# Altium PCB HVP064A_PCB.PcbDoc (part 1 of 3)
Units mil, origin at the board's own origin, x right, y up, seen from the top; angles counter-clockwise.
Board outline 5750 x 4500 mil, 2 copper layers (Top Layer, Bottom Layer), stack 62 mil thick; 174 components, 71 nets, 376 pads, 361 vias.
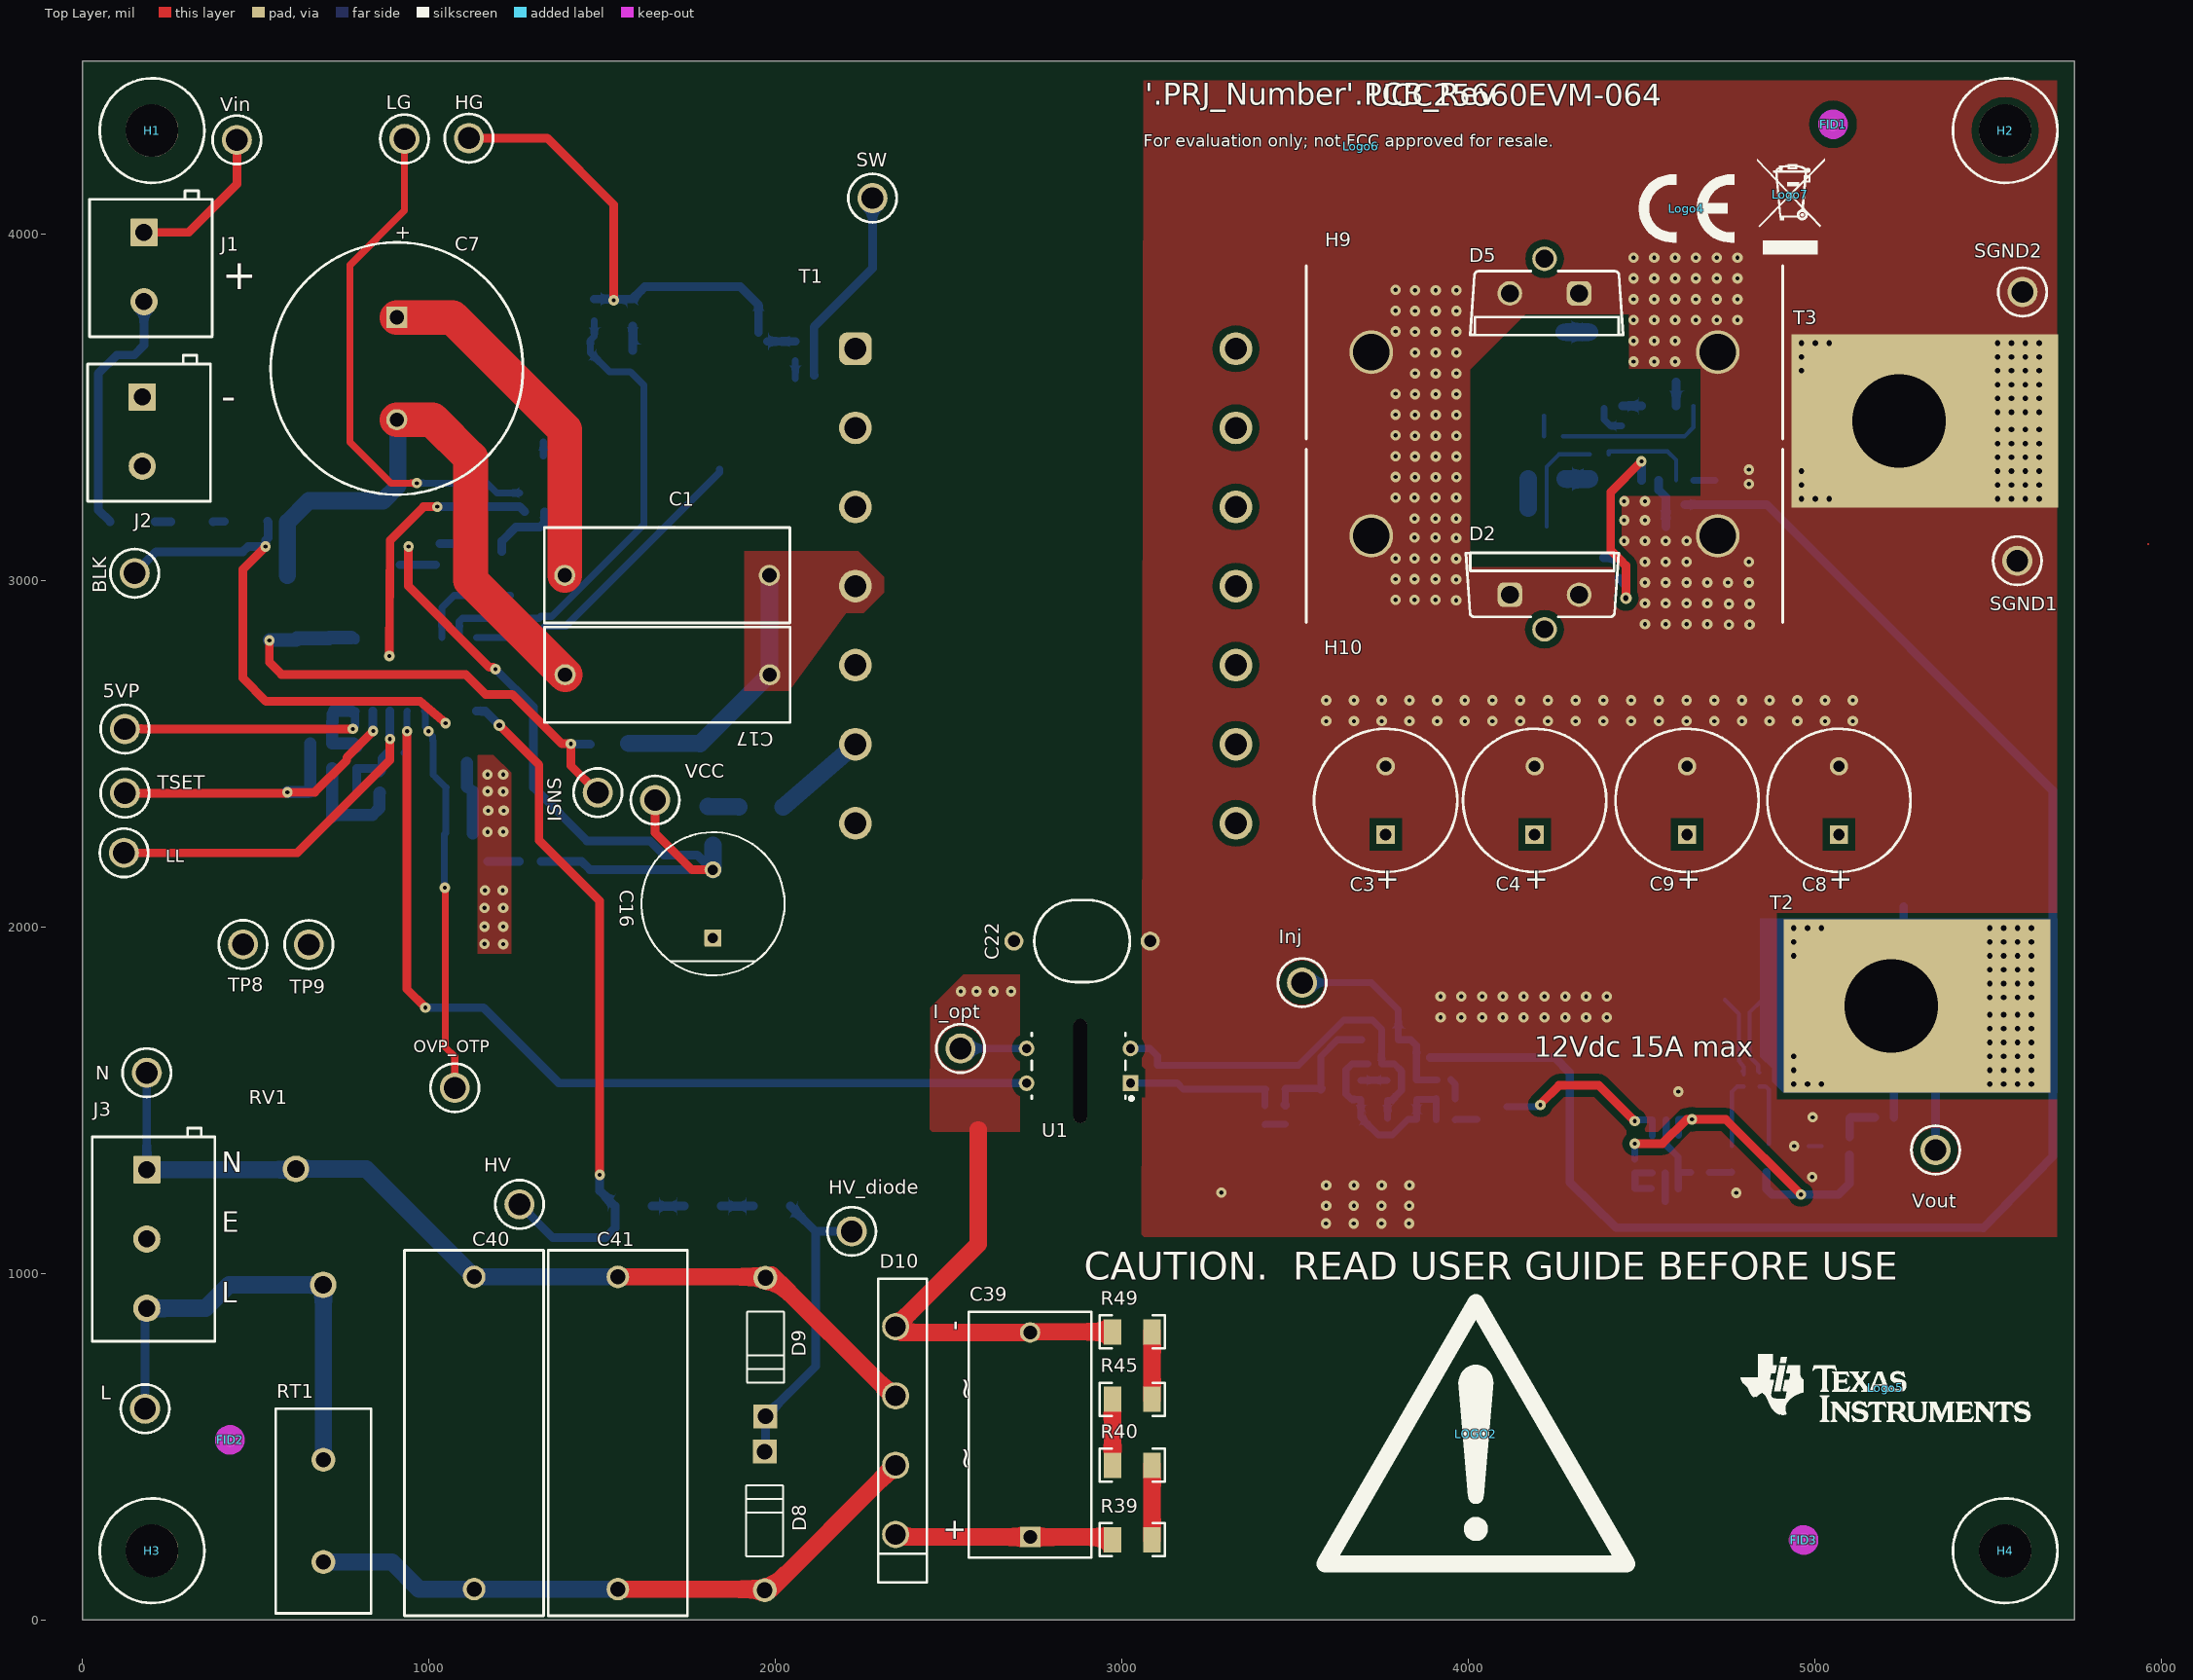
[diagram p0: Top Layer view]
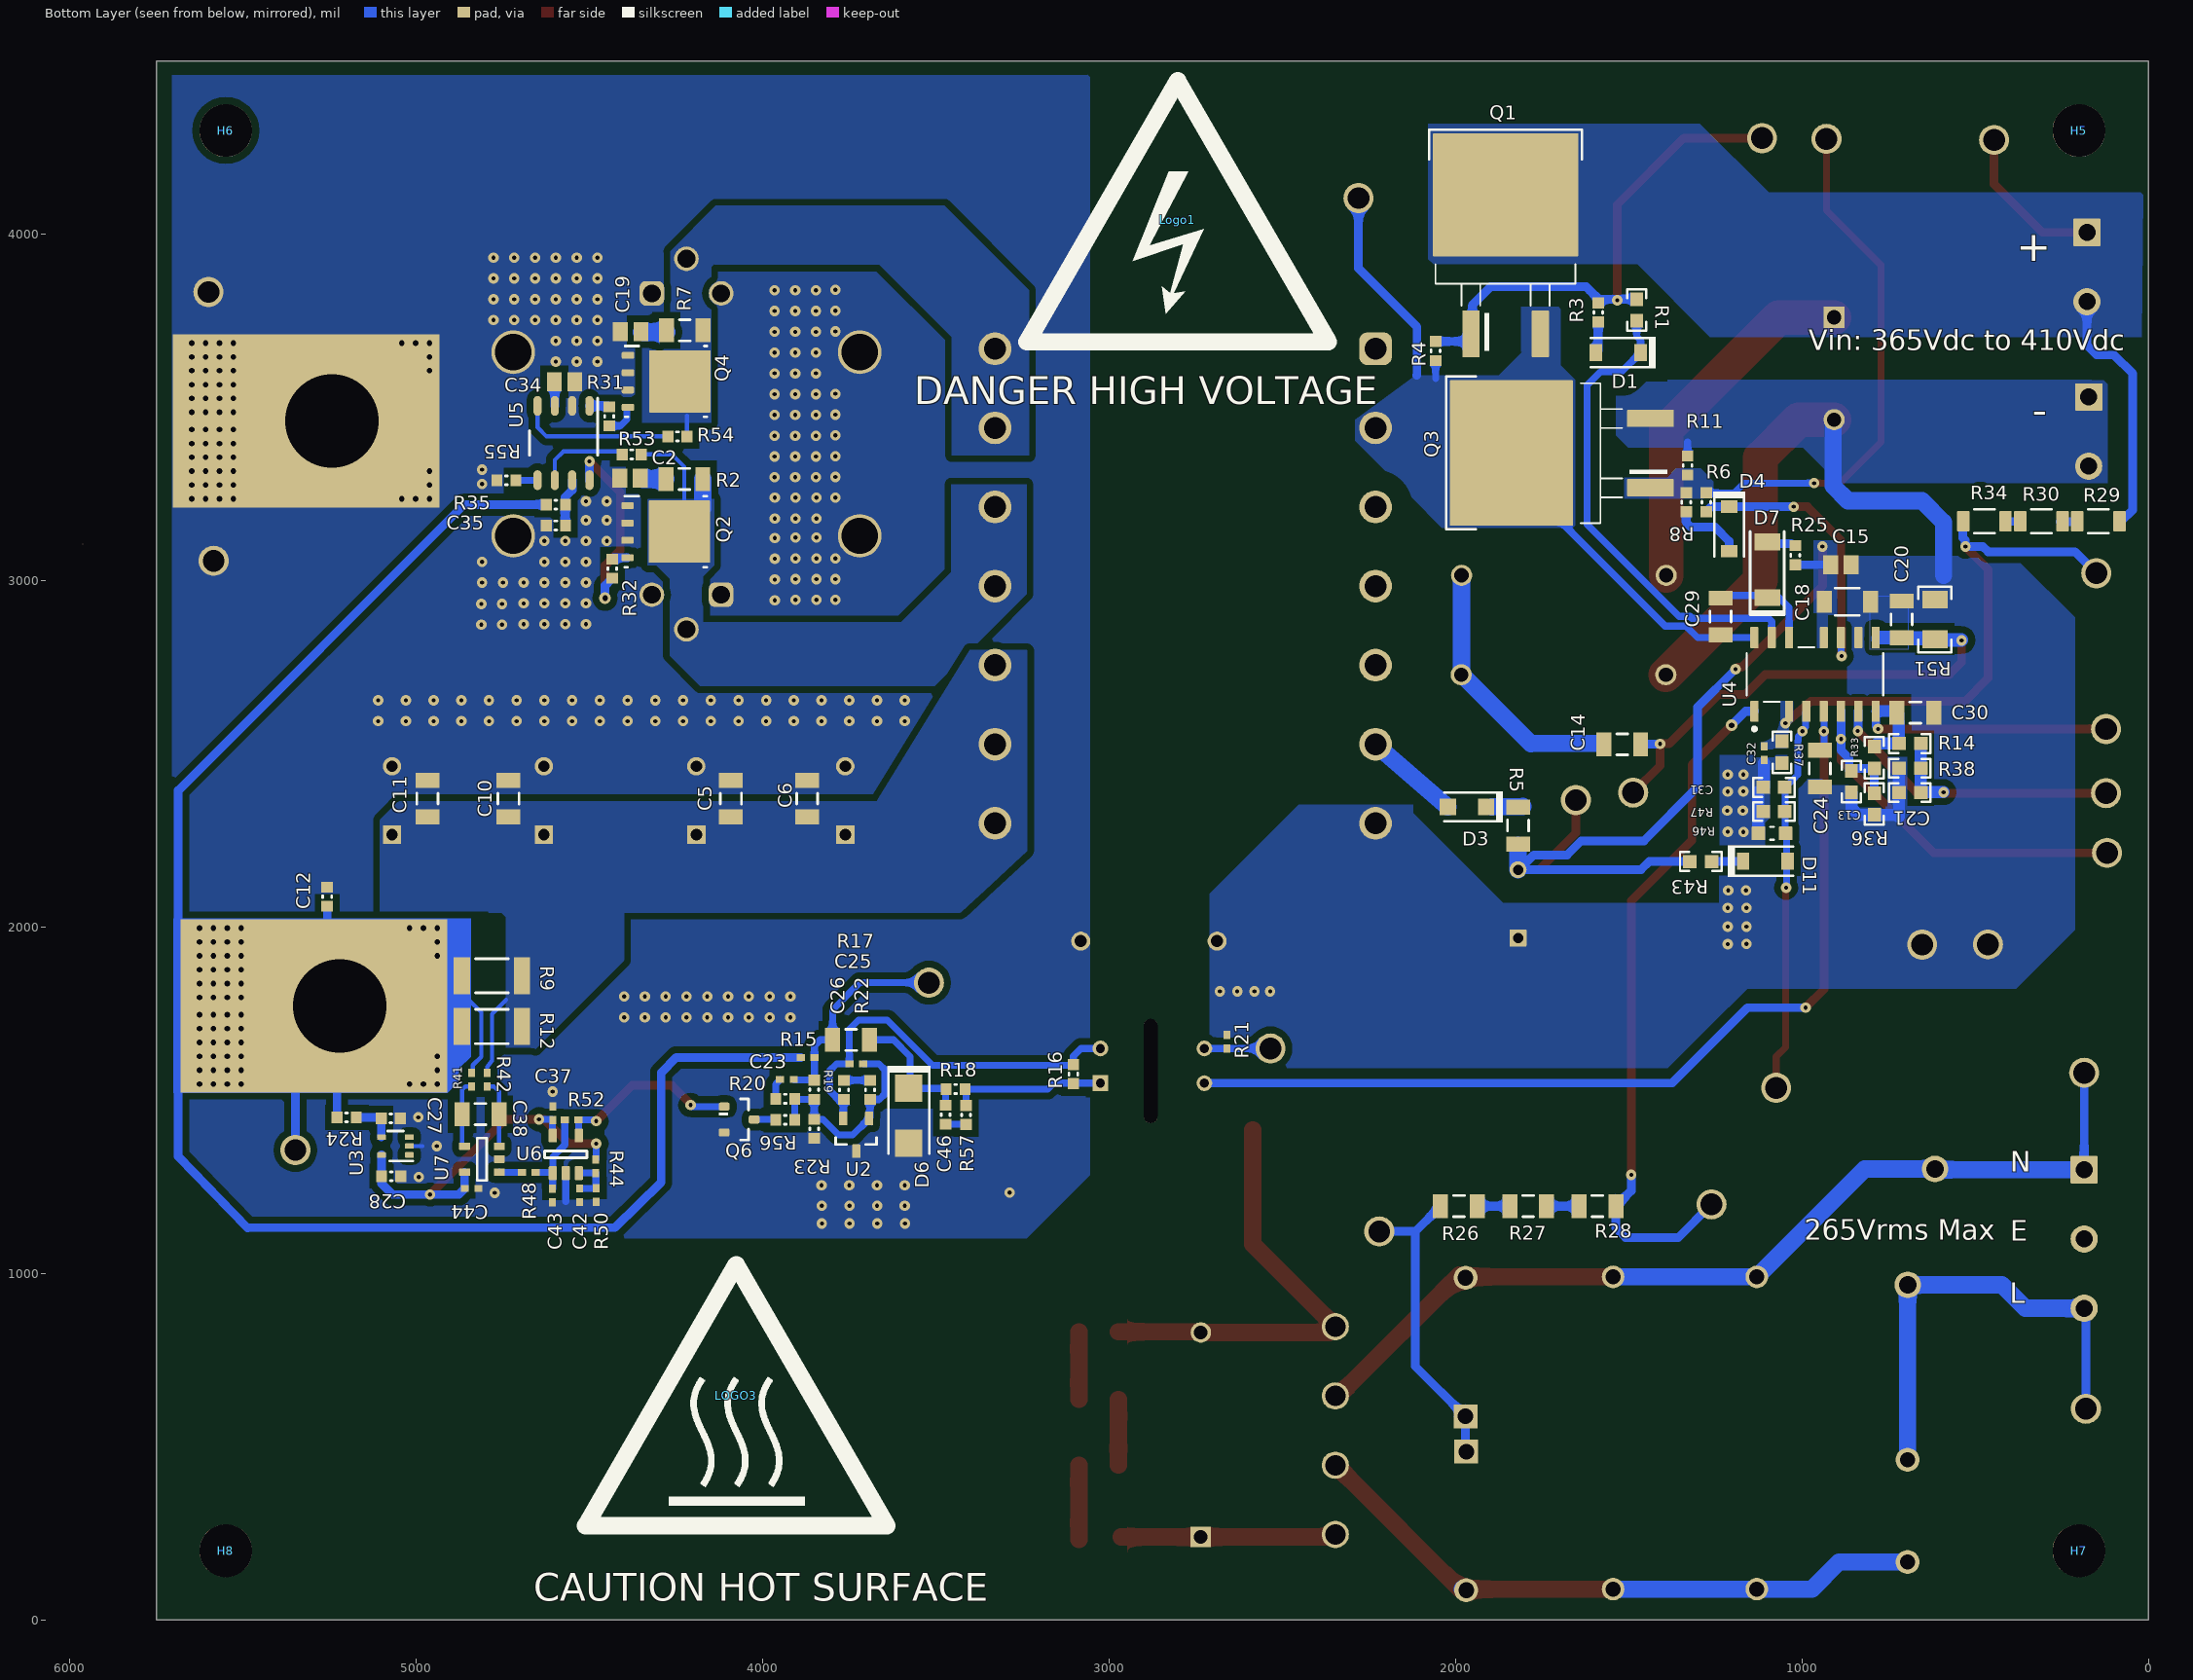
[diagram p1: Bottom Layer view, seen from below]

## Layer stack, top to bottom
Top Solder: solder mask 0.4, Solder Resist, Dk 3.5
Top Layer: signal copper 2.8
Dielectric1: core 56.4, FR-4 High Tg, Dk 4.8
Bottom Layer: signal copper 2.8
Bottom Solder: solder mask 0.4, Solder Resist, Dk 3.5

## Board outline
0,0 5750,0 5750,4500 0,4500

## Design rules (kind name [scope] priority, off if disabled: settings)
AcuteAngle [All] p1: minimum=4.50000000000000E+0001 checktracksonly=FALSE
AssemblyTestPointUsage [All] p1: valid=2
Clearance Clearance_2 [InNetClass('HV') vs Not InNetClass('HV')] p1: gap=60 ignorepadtopadclearanceinfootprint=TRUE except(0: Arc-Hole Track-Hole SMDPad-Hole THPad-Hole Via-Hole Fill-Hole Poly-Hole Region-Hole Text-Hole)
Clearance Clearance_1 [InNetClass('MV') vs Not InNetClass('MV')] p2: gap=40 ignorepadtopadclearanceinfootprint=TRUE
Clearance Clearance_Keepouts [((IsTrack Or IsArc) And Not InPoly) And IsFree and IsKeepOut vs ((IsTrack Or IsArc) And Not InPoly) And IsFree and IsKeepOut] p3: gap=0 ignorepadtopadclearanceinfootprint=FALSE
Clearance Clearance_BoardEdge_MountingHoles [OnCopper and InComponentClass('Mounting Holes') vs IsKeepOut] p4: gap=40 ignorepadtopadclearanceinfootprint=FALSE except(0: Arc-Hole Track-Hole SMDPad-Hole THPad-Hole Via-Hole Fill-Hole Poly-Hole Region-Hole Text-Hole)
Clearance Clearance_BoardEdge_Poly [OnCopper and InPoly vs IsKeepOut] p5: gap=25 ignorepadtopadclearanceinfootprint=FALSE except(0: Arc-Hole Track-Hole SMDPad-Hole THPad-Hole Via-Hole Fill-Hole Poly-Hole Region-Hole Text-Hole)
Clearance Clearance_BoardEdge [OnCopper and Not InComponentClass('Logo') and not InComponentClass('FiducialMark') and not InRegion(1000,500,4000,800) and Not IsKeepout vs IsKeepOut] p6: gap=75 ignorepadtopadclearanceinfootprint=FALSE except(0: Arc-Hole Track-Hole SMDPad-Hole THPad-Hole Via-Hole Fill-Hole Poly-Hole Region-Hole Text-Hole)
Clearance Clearance_Poly [InPolygon] p7: gap=20 ignorepadtopadclearanceinfootprint=FALSE except(0: Arc-Hole Track-Hole SMDPad-Hole THPad-Hole Via-Hole Fill-Hole Poly-Hole Region-Hole Text-Hole)
Clearance [All] p8: gap=7.87 ignorepadtopadclearanceinfootprint=FALSE except(0: Arc-SMDPad Arc-Hole Track-Hole SMDPad-Hole THPad-Hole Via-Hole Fill-Hole Poly-Hole Region-Hole Text-Hole)
ComponentClearance ComponentClearance_MountingHoles_FiducialMarks [InComponentClass('Mounting Holes') vs InComponentClass('FiducialMark')] p1: gap=20 collisioncheckmode=3 verticalgap=7 showdistances=FALSE
ComponentClearance ComponentClearance_Shunt [InComponentClass('Header') vs InComponentClass('Shunt')] p2: gap=0 collisioncheckmode=3 verticalgap=0 showdistances=FALSE
ComponentClearance ComponentClearance_Logo [InComponentClass('Logo')] p3: gap=5 collisioncheckmode=3 verticalgap=10 showdistances=FALSE
ComponentClearance ComponentClearance_ScrewToNut [(HasFootprint('KEYSTONE_4824')) vs (HasFootprint('Keystone_1903C'))] p4: gap=0 collisioncheckmode=3 verticalgap=0 showdistances=FALSE
ComponentClearance ComponentClearance_MountingHoles [InComponentClass('Mounting Holes')] p5: gap=20 collisioncheckmode=3 verticalgap=7 showdistances=FALSE
ComponentClearance ComponentClearance_SmallPassives [HasFootprint('0201*') or HasFootprint('0402*') or HasFootprint('0508') or HasFootprint('0603*') or HasFootprint('0612') or HasFootprint('0805*') or HasFootprint('0815*') or HasFootprint('0830*') or HasFootprint('1206*') or HasFootprint('1210*') or HasFootprint('1808*') or HasFootprint('1812*') or HasFootprint('1825*') or HasFootprint('2010*') or HasFootprint('2220*') or HasFootprint('2225*') or HasFootprint('2512*') or HasFootprint('2728*') or HasFootprint('3518*') vs HasFootprint('0201*') or HasFootprint('0402*') or HasFootprint('0508') or HasFootprint('0603*') or HasFootprint('0612') or HasFootprint('0805*') or HasFootprint('0815*') or HasFootprint('0830*') or HasFootprint('1206*') or HasFootprint('1210*') or HasFootprint('1808*') or HasFootprint('1812*') or HasFootprint('1825*') or HasFootprint('2010*') or HasFootprint('2220*') or HasFootprint('2225*') or HasFootprint('2512*') or HasFootprint('2728*') or HasFootprint('3518*')] p6: gap=20 collisioncheckmode=3 verticalgap=20 showdistances=FALSE
ComponentClearance ComponentClearance_THtoSMT [IsThruComponent vs IsSMTComponent] p7: gap=10 collisioncheckmode=3 verticalgap=7 showdistances=FALSE
ComponentClearance ComponentClearance_THtoTH [IsThruComponent vs IsThruComponent] p8: gap=10 collisioncheckmode=3 verticalgap=7 showdistances=FALSE
ComponentClearance [All] p9: gap=10 collisioncheckmode=3 verticalgap=7 showdistances=FALSE
DiffPairsRouting [All] p1: maxlimit=100 minlimit=10 mostfreqgap=10 toplayer_minwidth=15 toplayer_maxwidth=15 toplayer_prefwidth=15 bottomlayer_minwidth=15 bottomlayer_maxwidth=15 bottomlayer_prefwidth=15 maxuncoupledlength=1000
FabricationTestPointUsage TestPointUsage [All] p1: valid=2 allowmultiple=FALSE
FabricationTestpoint Testpoint [All] p1: side=3 testpointundercomponent=TRUE minsize=40 maxsize=100 preferedsize=60 minholesize=0 maxholesize=40 preferedholesize=32 testpointgrid=1 allowsidetop=TRUE allowsidebottom=TRUE usegrid=TRUE gridtolerance=0.01
FanoutControl Fanout_LCC [IsLCC] p1: bgadir=Out bgaviamode=Centered fanoutstyle=Auto fanoutdirection=Alternating viagrid=1 // Fanout_LCC (Default Rule)
FanoutControl Fanout_BGA [IsBGA] p2: bgadir=Out bgaviamode=Centered fanoutstyle=Auto fanoutdirection=Alternating viagrid=1 // Fanout_BGA (Default Rule)
FanoutControl Fanout_Default [All] p4: bgadir=Out bgaviamode=Centered fanoutstyle=Auto fanoutdirection=Alternating viagrid=1 // Fanout_Default (Default Rule)
FanoutControl Fanout_Small [(CompPinCount < 5)] p5: bgadir=Out bgaviamode=Centered fanoutstyle=Auto fanoutdirection=OutThenIn viagrid=1 // Fanout_Small (Default Rule)
Height [All] p1: minheight=0 maxheight=3000 prefheight=500
HoleSize [All] p1: absolutevalues=TRUE maxlimit=501 minlimit=7 maxpercent=80.000 minpercent=20.000
MinimumAnnularRing MinimumAnnularRing_ThermalPadVias [IsVia and InAnyComponent] p1: minimumring=5.91
MinimumAnnularRing [All] p2: minimumring=5
MinimumSolderMaskSliver MinimumSolderMaskSliver_Logo [InComponentClass('Logo') vs InComponentClass('Logo')] p1: minsoldermaskwidth=0.7
MinimumSolderMaskSliver [All] p2: minsoldermaskwidth=3
PlaneConnect [All] p1: planeconnectstyle=Direct reliefexpansion=10 reliefentries=4 reliefconductorwidth=10 reliefairgap=10
PolygonConnect PolygonConnect_16 [All vs IsNamedPolygon('C106_2') Or  IsNamedPolygon('Vout') Or  IsNamedPolygon('IN+') Or  IsNamedPolygon('Q203_5') Or  IsNamedPolygon('IN+') Or  IsNamedPolygon('Q201_5') Or  IsNamedPolygon('C108_2') Or  IsNamedPolygon('SGND') Or  IsNamedPolygon('IN+') Or  IsNamedPolygon('SGND') Or  IsNamedPolygon('Q203_5') Or  IsNamedPolygon('IN+') Or  IsNamedPolygon('SGND') Or  IsNamedPolygon('GND') Or  IsNamedPolygon('C113_2') Or  IsNamedPolygon('C107_2') Or  IsNamedPolygon('C107_2') Or  IsNamedPolygon('Vout') Or  IsNamedPolygon('SIGNAL_LAYER_1_GND_P074') Or  IsNamedPolygon('HV') Or  IsNamedPolygon('C108_2') Or  IsNamedPolygon('C103_2') Or  IsNamedPolygon('Q201_5') Or  IsNamedPolygon('Vout') Or  IsNamedPolygon('C109_2') Or  IsNamedPolygon('Q201_5') Or  IsNamedPolygon('GND') Or  IsNamedPolygon('C107_2') Or  IsNamedPolygon('C102_1') Or  IsNamedPolygon('GND') Or  IsNamedPolygon('SGND') Or  IsNamedPolygon('HS') Or  IsNamedPolygon('Q203_5') Or  IsNamedPolygon('Q201_5') Or  IsNamedPolygon('Q203_5')] p1: connectstyle=Direct reliefconductorwidth=10 reliefentries=4 polygonreliefangle="90 Angle" airgapwidth=10
PolygonConnect PolygonConnect_15 [All vs IsNamedPolygon('C109_2') Or  IsNamedPolygon('C107_2') Or  IsNamedPolygon('HV') Or  IsNamedPolygon('Q203_5') Or  IsNamedPolygon('C107_2') Or  IsNamedPolygon('HS') Or  IsNamedPolygon('Q201_5') Or  IsNamedPolygon('Q203_5') Or  IsNamedPolygon('C106_2') Or  IsNamedPolygon('C108_2') Or  IsNamedPolygon('Vout') Or  IsNamedPolygon('Q203_5') Or  IsNamedPolygon('C108_2') Or  IsNamedPolygon('C113_2') Or  IsNamedPolygon('Q203_5') Or  IsNamedPolygon('Q201_5') Or  IsNamedPolygon('C107_2') Or  IsNamedPolygon('C102_1') Or  IsNamedPolygon('SGND') Or  IsNamedPolygon('GND') Or  IsNamedPolygon('SGND') Or  IsNamedPolygon('GND') Or  IsNamedPolygon('IN+') Or  IsNamedPolygon('IN+') Or  IsNamedPolygon('Q201_5') Or  IsNamedPolygon('Q201_5') Or  IsNamedPolygon('SGND') Or  IsNamedPolygon('SGND') Or  IsNamedPolygon('Vout') Or  IsNamedPolygon('Vout') Or  IsNamedPolygon('IN+') Or  IsNamedPolygon('GND') Or  IsNamedPolygon('IN+') Or  IsNamedPolygon('GND')] p2: connectstyle=Direct reliefconductorwidth=10 reliefentries=4 polygonreliefangle="90 Angle" airgapwidth=10
PolygonConnect PolygonConnect_14 [All vs IsNamedPolygon('C106_2') Or  IsNamedPolygon('C107_2') Or  IsNamedPolygon('C107_2') Or  IsNamedPolygon('C107_2') Or  IsNamedPolygon('C102_1') Or  IsNamedPolygon('Q203_5') Or  IsNamedPolygon('Vout') Or  IsNamedPolygon('Q203_5') Or  IsNamedPolygon('Q203_5') Or  IsNamedPolygon('Q201_5') Or  IsNamedPolygon('C108_2') Or  IsNamedPolygon('Q203_5') Or  IsNamedPolygon('HS') Or  IsNamedPolygon('HV') Or  IsNamedPolygon('C108_2') Or  IsNamedPolygon('Q201_5') Or  IsNamedPolygon('C109_2') Or  IsNamedPolygon('Q201_5') Or  IsNamedPolygon('Q201_5') Or  IsNamedPolygon('C113_2')] p3: connectstyle=Direct reliefconductorwidth=10 reliefentries=4 polygonreliefangle="90 Angle" airgapwidth=10
PolygonConnect PolygonConnect_13 [All vs IsNamedPolygon('C102_1') Or  IsNamedPolygon('HV') Or  IsNamedPolygon('C107_2') Or  IsNamedPolygon('C109_2') Or  IsNamedPolygon('C107_2') Or  IsNamedPolygon('C108_2') Or  IsNamedPolygon('C106_2') Or  IsNamedPolygon('C108_2') Or  IsNamedPolygon('C113_2') Or  IsNamedPolygon('C107_2')] p4: connectstyle=Direct reliefconductorwidth=10 reliefentries=4 polygonreliefangle="90 Angle" airgapwidth=10
PolygonConnect PolygonConnect_12 [All vs IsNamedPolygon('C107_2') Or  IsNamedPolygon('C113_2') Or  IsNamedPolygon('C106_2') Or  IsNamedPolygon('C107_2') Or  IsNamedPolygon('C107_2') Or  IsNamedPolygon('C102_1')] p5: connectstyle=Direct reliefconductorwidth=10 reliefentries=4 polygonreliefangle="90 Angle" airgapwidth=10
PolygonConnect PolygonConnect_11 [All vs IsNamedPolygon('C106_2') Or  IsNamedPolygon('C102_1') Or  IsNamedPolygon('C107_2') Or  IsNamedPolygon('C107_2') Or  IsNamedPolygon('C107_2')] p6: connectstyle=Direct reliefconductorwidth=10 reliefentries=4 polygonreliefangle="90 Angle" airgapwidth=10
PolygonConnect PolygonConnect_10 [All vs IsNamedPolygon('C106_2')] p7: connectstyle=Direct reliefconductorwidth=10 reliefentries=4 polygonreliefangle="90 Angle" airgapwidth=10
PolygonConnect PolygonConnect_9 [All vs IsNamedPolygon('C11_1') Or  IsNamedPolygon('Vin') Or  IsNamedPolygon('Vin') Or  IsNamedPolygon('5V') Or  IsNamedPolygon('D6_2') Or  IsNamedPolygon('Q3_3') Or  IsNamedPolygon('GND2') Or  IsNamedPolygon('GND2') Or  IsNamedPolygon('GND') Or  IsNamedPolygon('Q3_4') Or  IsNamedPolygon('12V5') Or  IsNamedPolygon('GND') Or  IsNamedPolygon('12V5') Or  IsNamedPolygon('D3_1')] p8: connectstyle=Direct reliefconductorwidth=10 reliefentries=4 polygonreliefangle="90 Angle" airgapwidth=10
PolygonConnect PolygonConnect_8 [All vs IsNamedPolygon('C11_1') Or  IsNamedPolygon('Vin') Or  IsNamedPolygon('12V5') Or  IsNamedPolygon('Q3_3') Or  IsNamedPolygon('GND2') Or  IsNamedPolygon('GND2') Or  IsNamedPolygon('5V') Or  IsNamedPolygon('Q3_4') Or  IsNamedPolygon('12V5')] p9: connectstyle=Direct reliefconductorwidth=10 reliefentries=4 polygonreliefangle="90 Angle" airgapwidth=10
PolygonConnect PolygonConnect_7 [All vs IsNamedPolygon('GND2') Or  IsNamedPolygon('GND2') Or  IsNamedPolygon('5V') Or  IsNamedPolygon('12V5') Or  IsNamedPolygon('12V5') Or  IsNamedPolygon('C11_1')] p10: connectstyle=Direct reliefconductorwidth=10 reliefentries=4 polygonreliefangle="90 Angle" airgapwidth=10
PolygonConnect PolygonConnect_6 [All vs IsNamedPolygon('GND2') Or  IsNamedPolygon('SGND') Or  IsNamedPolygon('GND1') Or  IsNamedPolygon('C901_1') Or  IsNamedPolygon('SGND') Or  IsNamedPolygon('GND2') Or  IsNamedPolygon('GND1')] p11: connectstyle=Direct reliefconductorwidth=10 reliefentries=4 polygonreliefangle="90 Angle" airgapwidth=10
PolygonConnect PolygonConnect_5 [All vs IsNamedPolygon('GND1') Or  IsNamedPolygon('GND1')] p12: connectstyle=Direct reliefconductorwidth=10 reliefentries=4 polygonreliefangle="90 Angle" airgapwidth=10
PolygonConnect PolygonConnect_4 [All vs IsNamedPolygon('C21_1') Or  IsNamedPolygon('C5_1') Or  IsNamedPolygon('C12_2') Or  IsNamedPolygon('C2_2') Or  IsNamedPolygon('C13_1') Or  IsNamedPolygon('C28_1') Or  IsNamedPolygon('C6_1') Or  IsNamedPolygon('GND') Or  IsNamedPolygon('GND2') Or  IsNamedPolygon('C14_1') Or  IsNamedPolygon('C13_1') Or  IsNamedPolygon('Q1_3') Or  IsNamedPolygon('C14_1') Or  IsNamedPolygon('C5_1') Or  IsNamedPolygon('GND2') Or  IsNamedPolygon('C28_1') Or  IsNamedPolygon('D5_2') Or  IsNamedPolygon('D6_2') Or  IsNamedPolygon('D2_1') Or  IsNamedPolygon('C12_2') Or  IsNamedPolygon('D2_1') Or  IsNamedPolygon('C4_1') Or  IsNamedPolygon('C4_1') Or  IsNamedPolygon('C2_2') Or  IsNamedPolygon('GND') Or  IsNamedPolygon('C33_1') Or  IsNamedPolygon('C9_1')] p13: connectstyle=Direct reliefconductorwidth=10 reliefentries=4 polygonreliefangle="90 Angle" airgapwidth=10
PolygonConnect PolygonConnect_3 [All vs IsNamedPolygon('C28_1') Or  IsNamedPolygon('C12_2') Or  IsNamedPolygon('C28_1') Or  IsNamedPolygon('C9_1') Or  IsNamedPolygon('D5_2') Or  IsNamedPolygon('C12_2') Or  IsNamedPolygon('C2_2') Or  IsNamedPolygon('C14_1') Or  IsNamedPolygon('C4_1') Or  IsNamedPolygon('C14_1') Or  IsNamedPolygon('D6_2') Or  IsNamedPolygon('GND2') Or  IsNamedPolygon('Q1_3') Or  IsNamedPolygon('C5_1') Or  IsNamedPolygon('D2_1') Or  IsNamedPolygon('C4_1') Or  IsNamedPolygon('C13_1') Or  IsNamedPolygon('C5_1') Or  IsNamedPolygon('C13_1') Or  IsNamedPolygon('C33_1') Or  IsNamedPolygon('D2_1') Or  IsNamedPolygon('GND') Or  IsNamedPolygon('GND') Or  IsNamedPolygon('GND2') Or  IsNamedPolygon('C2_2') Or  IsNamedPolygon('C6_1') Or  IsNamedPolygon('C21_1')] p14: connectstyle=Direct reliefconductorwidth=10 reliefentries=4 polygonreliefangle="90 Angle" airgapwidth=10
PolygonConnect PolygonConnect_2 [All vs IsNamedPolygon('C21_1') Or  IsNamedPolygon('C4_1') Or  IsNamedPolygon('D5_2') Or  IsNamedPolygon('C5_1') Or  IsNamedPolygon('C14_1') Or  IsNamedPolygon('C13_1') Or  IsNamedPolygon('C4_1') Or  IsNamedPolygon('C33_1') Or  IsNamedPolygon('C12_2') Or  IsNamedPolygon('D2_1') Or  IsNamedPolygon('C2_2') Or  IsNamedPolygon('C28_1') Or  IsNamedPolygon('C12_2') Or  IsNamedPolygon('D2_1') Or  IsNamedPolygon('C5_1') Or  IsNamedPolygon('Q1_3') Or  IsNamedPolygon('GND') Or  IsNamedPolygon('D6_2') Or  IsNamedPolygon('C6_1') Or  IsNamedPolygon('C2_2') Or  IsNamedPolygon('C14_1') Or  IsNamedPolygon('C28_1') Or  IsNamedPolygon('C13_1') Or  IsNamedPolygon('C9_1') Or  IsNamedPolygon('GND')] p15: connectstyle=Direct reliefconductorwidth=10 reliefentries=4 polygonreliefangle="90 Angle" airgapwidth=10
PolygonConnect PolygonConnect_1 [All vs IsNamedPolygon('C28_1') Or  IsNamedPolygon('D5_2') Or  IsNamedPolygon('C5_1') Or  IsNamedPolygon('C5_1') Or  IsNamedPolygon('D2_1') Or  IsNamedPolygon('C21_1') Or  IsNamedPolygon('C9_1') Or  IsNamedPolygon('C4_1') Or  IsNamedPolygon('C14_1') Or  IsNamedPolygon('C28_1') Or  IsNamedPolygon('C6_1') Or  IsNamedPolygon('C12_2') Or  IsNamedPolygon('C33_1') Or  IsNamedPolygon('C4_1') Or  IsNamedPolygon('C13_1') Or  IsNamedPolygon('C12_2') Or  IsNamedPolygon('D6_2') Or  IsNamedPolygon('C2_2') Or  IsNamedPolygon('C14_1') Or  IsNamedPolygon('D2_1') Or  IsNamedPolygon('C2_2') Or  IsNamedPolygon('C13_1')] p16: connectstyle=Direct reliefconductorwidth=10 reliefentries=4 polygonreliefangle="90 Angle" airgapwidth=10
PolygonConnect [All] p17: connectstyle=Direct reliefconductorwidth=10 reliefentries=4 polygonreliefangle="90 Angle" airgapwidth=10
RoutingVias ThermalPadVias [IsVia and not InNet('SGND')and not InNet('Vout')] p1: holewidth=7.87 width=19.68 viastyle="Through Hole" minholewidth=7.87 minwidth=19.68 maxholewidth=17 maxwidth=35
RoutingVias [IsVia and not InNet('SGND')and not InNet('Vout')] p2: holewidth=16 width=34 viastyle="Through Hole" minholewidth=7.87 minwidth=20 maxholewidth=40 maxwidth=65
SilkToBoardRegionClearance [Not ((IsComment or IsDesignator) And (Hide <> 'False')) and not InRegion(1000,500,4000,800)] p1:
SilkToSilkClearance SilkToSilkClearance_Pb-FreeLogo [(HasFootprint('Pb-Free_Overlay_Medium') OR HasFootprint('Pb-Free_Overlay_Small')) vs (HasFootprint('Pb-Free_Overlay_Medium') OR HasFootprint('Pb-Free_Overlay_Small'))] p1: silktosilkclearance=0
SilkToSilkClearance [All] p2: silktosilkclearance=3
SilkToSolderMaskClearance "Silk to Solder Mask Opening" [All] p1: minsilkscreentomaskgap=1 clearancetoexposedcopper=FALSE
SolderMaskExpansion [All] p1: expansion=1.97 istentingtop=FALSE
UnpouredPolygon [All] p1: allowunpoured=TRUE allowshelved=TRUE
Width [All] p1: maxlimit=100 minlimit=6 preferedwidth=10 checkconnectedcopper=TRUE
13 further rules are at their usual default settings.

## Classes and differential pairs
net class MV: NetR29_1 NetR30_1
net class HV: HO HS NetC1_2 NetC29_1 NetC39_1 NetC40_1 NetC40_2 NetD1_2 NetD8_1 NetHG_1 NetHV_1 NetJ3_3 VIN
component class HVP064A_Control: 5VP BLK C13 C21 C27 C28 C29 C30 C31 C32 C34 C35 C37 C38 C39 C40 C41 C42 C43 C44 D7 D8 D9 D10 D11 HV HV_diode J3 L LL N OVP_OTP R14 R24 R25 R26 R27 R28 R29 R30 R31 R32 R33 R34 R35 R36 R37 R38 R39 R40 R41 R42 R43 R44 R45 R46 R47 R48 R49 R50 R52 R53 R54 R55 RT1 RV1 TSET U3 U4 U5 U6 U7
component class HVP064A_PowerStage: C1 C2 C3 C4 C5 C6 C7 C8 C9 C10 C11 C12 C14 C15 C16 C17 C18 C19 C20 C22 C23 C24 C25 C26 C46 D1 D2 D3 D4 D5 D6 H9 H10 HG I_opt Inj ISNS J1 J2 LG Q1 Q2 Q3 Q4 Q6 R1 R2 R3 R4 R5 R6 R7 R8 R9 R11 R12 R15 R16 R17 R18 R19 R20 R21 R22 R23 R51 R56 R57 SGND1 SGND2 SW T1 T2 T3 TP8 TP9 U1 U2 VCC Vin Vout
component class AssemblyNote: ZZ1 ZZ2 ZZ3
component class FiducialMark: FID1 FID2 FID3
component class HVP064A_EVM_Hardware: FID1 FID2 FID3 H1 H2 H3 H4 H5 H6 H7 H8 Logo1 LOGO2 LOGO3 Logo4 LOGO4 Logo5 Logo6 Logo7 ZZ1 ZZ2 ZZ3
component class Logo: Logo5

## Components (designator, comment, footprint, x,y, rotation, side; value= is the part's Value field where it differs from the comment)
5VP "5010" Keystone5010 122,2572.19 r0 top
BLK "5012" Keystone5012 150,3022 r0 top
C1 "B32652A7153J000" B32652_1800x700x1250 1687,3016 r0 top value=0.015uF
C2 "GRM2165C2A122JA01D" 0805L 4383,3297 r0 bottom value=1200pF
C3 "UHW1V471MPD" HW_1000x1600 3761.61,2366.26 r90 top value=470uF
C4 "UHW1V471MPD" HW_1000x1600 4191.61,2366.26 r90 top value=470uF
C5 "C3216X5R1E226M160AB" 1206_190L 4091.61,2371.26 r270 bottom value=22uF
C6 "C3216X5R1E226M160AB" 1206_190L 3871.61,2371.26 r270 bottom value=22uF
C7 "EKXG451ELL680MMN3S" KXG_1800x3150 907,3613 r270 top value=68uF
C8 "UHW1V471MPD" HW_1000x1600 5070,2366.26 r90 top value=470uF
C9 "UHW1V471MPD" HW_1000x1600 4631.61,2366.26 r90 top value=470uF
C10 "C3216X5R1E226M160AB" 1206_190L 4734,2371.26 r90 bottom value=22uF
C11 "C3216X5R1E226M160AB" 1206_190L 4968,2371.26 r90 bottom value=22uF
C12 "06035A101FAT2A" 0603L 5257,2088 r90 bottom value=100pF
C13 "C0603X102K5RACTU" 0603 857.34,2420.41 r270 bottom value=1000pF
C14 "GRM31A5C2J151JW01D" 1206L 1518.58,2528 r180 bottom value=150pF
C15 "C2012X7R1V225K085AC" 0805L 886.87,3046.51 r180 bottom value=2.2uF
C16 "35ZL330MEFC10X16" FP-35ZL330MEFC10X16_RADIAL-MFG 1819.55,2067.71 r90 top value=330µF
C17 "B32652A7153J000" B32652_1800x700x1250 1688,2729 r180 top value=0.015uF
C18 "C1206C106J3RACAUTO" 1206_180 868.61,2939.49 r180 bottom value=10uF
C19 "GRM2165C2A122JA01D" 0805L 4381,3719 r0 bottom value=1200pF
C20 "12061A101JAT2A" 1206L 712,2888.61 r90 bottom value=100pF
C21 "C0603X221K5RACTU" 0603 688.17,2388.92 r0 bottom value=220pF
C22 "CD45-E2GA102M-NKA" CD45_700x600x1100 2885,1960 r180 top value=1000pF
C23 "885012005062" 0402L 3930,1560 r0 bottom value=150pF
C24 "C1206C302J5GACTU" 1206L 948.22,2458.12 r270 bottom value=3pF
C25 "885012005062" 0402L 3730,1605.68 r0 bottom value=150pF
C26 "06031C103JAT2A" 0603L 3765,1530.68 r270 bottom value=0.01uF
C27 "EMK107B7105KA-T" 0603L 5073.39,1448.33 r180 bottom value=1uF
C28 "EMK107B7105KA-T" 0603L 5072.39,1281.33 r180 bottom value=1uF
C29 "GRM31C5C1E104JA01L" 1206_180L 1235,2897 r270 bottom value=0.1uF
C30 "C3216X7R1E475K085AB" 1206L 672.42,2619.54 r180 bottom value=4.7uF
C31 "C0603X222K5RACTU" 0603 1080.51,2403.97 r0 bottom value=2200pF
C32 "C0402C103J5RACTU" 0402L 1108,2502.29 r270 bottom value=0.01uF
C34 "C2012X7R1V225K085AC" 0805L 4572,3575 r180 bottom value=2.2uF
C35 "GRM188R71C105KE15D" 0603L 4597,3160 r0 bottom value=1uF
C37 "GRM155R61C104KA88D" 0402L 4605.39,1463.33 r90 bottom value=0.1uF
C38 "12067A470JAT2A" 1206L 4814.39,1460.33 r180 bottom value=47pF
C39 "B32922C3474K" B32922_17.5mm 2735,535 r90 top value=0.47uF
C40 "R46KN410000P0M" R46_2650x1000x1850 1130,540 r90 top value=1uF
C41 "R46KN410000P0M" R46_2650x1000x1850 1545,540 r90 top value=1uF
C42 "GRM1555C1H101JA01D" 0402L 4528.39,1226.33 r90 bottom value=100pF
C43 "GRM1555C1H101JA01D" 0402L 4606.39,1225.33 r270 bottom value=100pF
C44 "GRM155R61E104KA87D" 0402L 4840.39,1245.33 r180 bottom value=0.1uF
C46 "C0603C472J1GAC7867" 0603L 3472,1459 r270 bottom value=4700pF
D1 "1N4148W-7-F" SOD-123 1530,3659 r0 bottom value=100V
D2 "STPS41H100CTY" TO-220AB_100mil 4220,2960 r0 top value=100V
D3 "PMEG10020ELRX" SOD-123W 1966.66,2347.2 r0 bottom value=100V
D4 "1N4148W-7-F" SOD-123 1210,3150 r270 bottom value=100V
D5 "STPS41H100CTY" TO-220AB_100mil 4220,3830 r180 top value=100V
D6 "1SMA5926BT3G" SMA 3578,1456 r270 bottom value=11V
D7 "ES1JAF" SMAF 1100,3032 r90 bottom value=600V
D8 "1N4007-E3/73" DO-41 1969,286 r270 top value=1000V
D9 "1N4007-E3/73" DO-41 1971,788 r90 top value=1000V
D10 "GBU8J-BP" GBU 2347,547 r90 top value=420V
D11 "DDZ15-7" SOD-123 1105.49,2190.74 r180 bottom value=15V
FID1 "Fiducial" Fiducial10-20 5053,4318 r0 top
FID2 "Fiducial" Fiducial10-20 425,520 r0 top
FID3 "Fiducial" Fiducial10-20 4968,231 r0 top
H1 "4824" KEYSTONE_4824 200,4300 r0 top locked
H2 "4824" KEYSTONE_4824 5550,4300 r0 top locked
H3 "4824" KEYSTONE_4824 200,200 r0 top locked
H4 "4824" KEYSTONE_4824 5550,200 r0 top
H5 "1903C" KEYSTONE_1903C 200,4300 r180 bottom locked
H6 "1903C" KEYSTONE_1903C 5550,4300 r180 bottom
H7 "1903C" KEYSTONE_1903C 200,200 r180 bottom locked
H8 "1903C" KEYSTONE_1903C 5550,200 r180 bottom locked
H9 "531202B02500G" 531202 4220,3660 r180 top
H10 "531202B02500G" 531202 4220,3130 r0 top
HG "5012" Keystone5012 1115,4278 r0 top
HV "5012" Keystone5012 1261,1200 r0 top
HV_diode "5012" Keystone5012 2220,1122 r0 top
I_opt "5012" Keystone5012 2534,1650 r0 top
Inj "5013" Keystone5013 3520,1840 r0 top
ISNS "5012" Keystone5012 1487.09,2388.7 r0 top
J1 "ED120/2DS" On-Shore_ED120_2DS 177,3906 r270 top
J2 "ED120/2DS" On-Shore_ED120_2DS 172,3431 r270 top
J3 "ED120/3DS" On-Shore_ED120_3DS 185,1100 r270 top
L "5012" Keystone5012 180,610 r0 top
LG "5012" Keystone5012 929,4276 r270 top
LL "5012" Keystone5012 119.24,2214.76 r0 top
Logo1 "DANGER HIGH VOLTAGE" IEC_HighVoltage_Large 2802,4042 r180 bottom (schematic designator LOGO1)
LOGO2 "CAUTION.  READ USER GUIDE BEFORE USE" IEC_Caution_Large 4022,537 r0 top (schematic designator Logo2)
LOGO3 "CAUTION HOT SURFACE" IEC_HotSurface_Large 4076.23,647.46 r180 bottom
Logo4 "CE Mark" CE_Mark_5mm 4630,4075 r0 top
Logo5 "Texas Instruments" TI_Stacked_Overlay_Small 5205,670 r0 top
Logo6 "FCC disclaimer" FCC_disclaimer 3690,4255 r0 top
Logo7 "WEEE logo" WEEE_Minimum 4930,4115 r0 top
N "5012" Keystone5012 185,1580 r0 top
OVP_OTP "5012" Keystone5012 1074.2,1536.5 r0 top
Q1 "IPB60R105CFD7ATMA1" DDPAK 1855,3959 r90 bottom
Q2 "CSD18511Q5A" DQJ0008A 4280,3142 r180 bottom value=40V
Q3 "IPB60R105CFD7ATMA1" DDPAK 1683,3369 r0 bottom
Q4 "CSD18511Q5A" DQJ0008A 4279,3576 r180 bottom value=40V
Q6 "2N7002K-T1-E3" SOT-23L 4068,1445 r180 bottom value=60V
R1 "RC0603FR-0742R2L" 0603 1477,3782 r90 bottom value=42.2
R2 "RC1206FR-0710RL" 1206L 4226,3294 r180 bottom value=10.0
R3 "RC0603FR-071RL" 0603L 1588,3775 r90 bottom value=1.00
R4 "RC0603FR-0751KL" 0603L 2057.36,3663.73 r90 bottom value=51.0k
R5 "ERJ-8GEY0R00V" 1206L 1819.55,2293.5 r90 bottom value=0
R6 "RC0603FR-0742R2L" 0603L 1276,3227 r90 bottom value=42.2
R7 "RC1206FR-0710RL" 1206L 4225,3723 r180 bottom value=10.0
R8 "RC0603FR-071RL" 0603L 1334,3227 r90 bottom value=1.00
R9 "CSNL2010FT5L00" 2010L 4781.39,1860 r0 bottom value=0.005
R11 "RC0603FR-0751KL" 0603L 1330,3333 r270 bottom value=51.0k
R12 "CSNL2010FT5L00" 2010L 4781.39,1713.39 r0 bottom value=0.005
R14 "RC0603FR-071ML" 0603 688.17,2530.47 r0 bottom value=1.00Meg
R15 "RC0402JR-070RL" 0402L 3870,1624 r0 bottom value=0
R16 "RC0603FR-072K05L" 0603L 3103,1576 r270 bottom value=2.05k
R17 "CRCW12060000Z0EAHP" 1206L 3745,1675 r0 bottom value=0
R18 "RC0603FR-079K09L" 0603L 3443,1533 r0 bottom value=9.09k
R19 "RC0603FR-07147KL" 0603L 3851,1531 r90 bottom value=147k
R20 "ERJ-3EKF1002V" 0603L 3935,1505 r0 bottom value=10.0k
R21 "ERJ-2RKF1002X" 0402L 2660,1670 r270 bottom value=10.0k
R22 "RC0603FR-0733K2L" 0603L 3690,1530.68 r90 bottom value=33.2k
R23 "RC0603FR-0716K9L" 0603L 3851,1418 r90 bottom value=16.9k
R24 "RC0603JR-070RL" 0603L 5201.21,1451.03 r180 bottom value=0
R25 "ERJ-3RQF2R2V" 0603L 1019.15,3073.95 r90 bottom value=2.20
R26 "CRCW12061K65FKEA" 1206L 1990,1195 r180 bottom value=1.65k
R27 "CRCW12061K65FKEA" 1206L 1790,1195 r180 bottom value=1.65k
R28 "CRCW12061K65FKEA" 1206L 1590,1195 r180 bottom value=1.65k
R29 "KTR18EZPF3304" FP-KTR18EZPF3304_1206-MFG 144.16,3172 r180 bottom
R30 "KTR18EZPF3304" FP-KTR18EZPF3304_1206-MFG 308.58,3172 r180 bottom
R31 "RC0603JR-070RL" 0603L 4443,3475 r90 bottom value=0
R32 "RC0603JR-070RL" 0603L 4434,3035 r90 bottom value=0
R33 "RC0603FR-07549KL" 0603 790.75,2489.62 r90 bottom value=549k
R34 "KTR18EZPF3304" FP-KTR18EZPF3304_1206-MFG 473,3172 r180 bottom
R35 "RC0603FR-0710RL" 0603L 4597,3220 r0 bottom value=10.0
R36 "RC0603FR-07140KL" 0603 790.75,2355.77 r90 bottom value=140k
R37 "RT0603BRD0735K7L" 0603 1057.21,2505.16 r90 bottom value=35.7k
R38 "RT0603BRD07191KL" 0603 688.17,2459.16 r180 bottom value=191k
R39 "CRCW120610M0JNEA" 1206 3030,232 r0 top value=10Meg
R40 "CRCW120610M0JNEA" 1206 3030,447 r180 top value=10Meg
R41 "CRCW04024R75FKED" 0402L 4840.39,1560.33 r90 bottom value=4.75
R42 "CRCW04024R75FKED" 0402L 4795.39,1560.33 r90 bottom value=4.75
R43 "RG1608P-153-B-T5" 0603 1291.76,2189.8 r0 bottom value=15.0k
R44 "ERJ-2RKF1003X" 0402L 4481.39,1310.33 r90 bottom value=100k
R45 "CRCW120610M0JNEA" 1206 3030,637 r0 top value=10Meg
R46 "B57371V2474J060" FP-B57371V2474J060_0603-MFG 1086.23,2271.16 r180 bottom value=470k
R47 "RG1608P-153-B-T5" 0603 1080.51,2334.15 r180 bottom value=15.0k
R48 "CRCW04025K11FKED" 0402L 4675.39,1292.33 r0 bottom value=5.11k
R49 "CRCW120610M0JNEA" 1206 3030,832 r180 top value=10Meg
R50 "CRCW04023K01FKED" 0402L 4480.39,1227.33 r90 bottom value=3.01k
R51 "RC1206FR-07205RL" 1206 616,2888.61 r270 bottom value=205
R52 "CRCW0402261KFKED" 0402L 4551.39,1444.33 r0 bottom value=261k
R53 "RT0603BRD07536RL" 0603L 4378,3365 r0 bottom value=536
R54 "RT0603BRD07536RL" 0603L 4246,3417 r180 bottom value=536
R55 "RC0603FR-0739R2L" 0603L 4740,3290 r0 bottom value=39.2
R56 "RC0603FR-0780K6L" 0603L 3935,1444 r0 bottom value=80.6k
R57 "RC0603FR-071K21L" 0603L 3413,1458.02 r270 bottom value=1.21k
RT1 "B57237S0479M000" S237 695,315 r270 top value=4.7
RV1 "TMOV20RP750E" Littelfuse_TMOV20RP750E 655,1135 r270 top
SGND1 "5011" Keystone5011 5585,3058 r0 top
SGND2 "5011" Keystone5011 5600,3834 r0 top
SW "5012" Keystone5012 2280,4105 r0 top
T1 "750320617" Wurth_750344018 2780,2985 r0 top
T2 "CXS70-14-C" Panduit_CXS70-14-C 5220.73,1772.33 r180 top
T3 "CXS70-14-C" Panduit_CXS70-14-C 5243.16,3461.62 r180 top
TP8 "5011" Keystone5011 462.74,1950.44 r0 top
TP9 "5011" Keystone5011 652.73,1949.94 r0 top
TSET "5012" Keystone5012 121.87,2387.26 r270 top
U1 "VO618A-3" DIP-4 2875,1600 r180 top
U2 "TLVH431ACDBZR" DBZ0003A_N 3730,1400.68 r270 bottom
U3 "TPS71550DCKR" DCK0005A_L 5060.39,1368.33 r0 bottom
U4 "UCC256601DDBR" DDB0014A-MFG 962,2730 r90 bottom
U5 "UCC24624DR" D0008A_N 4575,3398 r270 bottom
U6 "LMV331M5/NOPB" DBV0005A_N 4568.39,1344.33 r90 bottom
U7 "INA180A4IDBV" DBV0005A_L 4810.39,1330.33 r0 bottom
VCC "5010" Keystone5010 1652.45,2367.2 r0 top
Vin "5010" Keystone5010 445,4273 r0 top
Vout "5010" Keystone5010 5348.99,1356.9 r0 top
ZZ1 "These assemblies are ESD sensitive, ESD precautions shall be observed." AssemblyNote 445,5098 r0 top
ZZ2 "These assemblies must be clean and free from flux and all contaminants. Use of no clean flux is not acceptable." AssemblyNote 445,4900.56 r0 top
ZZ3 "These assemblies must comply with workmanship standards IPC-A-610 Class 2, unless otherwise specified." AssemblyNote 445,4812 r0 top

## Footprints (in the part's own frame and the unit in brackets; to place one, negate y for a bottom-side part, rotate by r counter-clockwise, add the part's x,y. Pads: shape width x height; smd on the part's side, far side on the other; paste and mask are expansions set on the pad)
0402L [mm] "0402 from SM-752 data"
  rect 0.6x0.5 smd: 1(-0.5,0) 2(0.5,0)
  body extent -0.55,-0.3 0.55,0.3, height 0.6
0603 [mm] "0603 from SM-752 data"
  rect 1x0.95 smd: 1(-0.8,0) 2(0.8,0)
  silkscreen extent -1.52,-0.69 1.52,0.69, body extent -0.87,-0.47 0.87,0.47, height 1
0603L [mm] "0603 from SM-752 data"
  rect 0.8x0.85 smd: 1(-0.7,0) 2(0.7,0)
  silkscreen extent -0.07,-0.33 0.07,0.33, body extent -0.87,-0.47 0.87,0.47, height 1
0805L [mm] "0805 from SM-752 data"
  rect 1.1x1.4 smd: 1(-0.75,0) 2(0.75,0)
  body extent -1.1,-0.72 1.1,0.72, height 1.45
1206 [mm] "1206 from SM-752 data"
  rect 1.3x1.85 smd: 1(-1.45,0) 2(1.45,0)
  silkscreen extent -2.4,-1.21 2.4,1.21, body extent -1.7,-0.9 1.7,0.9, height 1.35
1206_180 [mm] "1206_180"
  rect 1.1x1.6 smd: 1(-1.7,0) 2(1.7,0)
  silkscreen extent -0.9,-1 0.9,1, body extent -1.75,-0.95 1.75,0.95, height 1.8
1206_180L [mm] "1206_180"
  rect 1.1x1.75 smd: 1(-1.35,0) 2(1.35,0)
  silkscreen extent -0.4,-0.77 0.4,0.77, body extent -1.75,-0.95 1.75,0.95, height 1.8
1206_190L [mm] "1206_190"
  rect 1.1x1.75 smd: 1(-1.35,0) 2(1.35,0)
  silkscreen extent -0.4,-0.77 0.4,0.77, body extent -1.75,-0.95 1.75,0.95, height 1.9
1206L [mm] "1206 from SM-752 data"
  rect 1.1x1.75 smd: 1(-1.35,0) 2(1.35,0)
  silkscreen extent -0.4,-0.77 0.4,0.77, body extent -1.7,-0.9 1.7,0.9, height 1.35
2010L [mm]
  rect 1.2x2.7 smd: 1(-2.2,0) 2(2.2,0)
  silkscreen extent -1.2,-1.25 1.2,1.25, body extent -2.73,-1.45 2.73,1.45, height 1.66
531202 [mm] "TH, 2-Leads, Body 34.92x12.7mm, Pin Spacing 25.4mm"
  round 3.2 hole 2.67: 1(-12.7,0) 2(12.7,0)
  silkscreen extent -17.46,-6.35 17.46,6.35, body extent -17.46,-6.35 17.46,6.35, height 50.8
AssemblyNote [mil] "Assembly Note"
B32652_1800x700x1250 [mm] "TH, 2-Leads, Body 18x7mm, Pin Spacing 15mm"
  round 1.55 hole 1.05: 1(-7.5,0) 2(7.5,0)
  silkscreen extent -9,-3.5 9,3.5, body extent -9,-3.5 9,3.5, height 12.5
B32922_17.5mm [mm] "Epcos film capacitors, 15mm spacing"
  rect 1.5x1.5 hole 1: 1(-7.5,0)
  round 1.5 hole 1: 2(7.5,0)
  silkscreen extent -9,-4.5 9,4.5, body extent -9,-4.5 9,4.5, height 17.5
CD45_700x600x1100 [mm] "TH, 2-Leads, Dia 7mm, Pin Spacing 10 mm"
  round 1.4 hole 0.9: 1(-5,0) 2(5,0)
  silkscreen extent -3.5,-3 3.5,3, body extent -5.34,-3.02 5.34,3.02, height 11
CE_Mark_5mm [mil] "Minimum text height for CE Mark"
  silkscreen extent -138,-98 138,98
D0008A_N [mm] "SOIC, 8-Leads, Body 4.9x3.9mm, Pitch 1.27mm, IPC Medium Density"
  oval 1.45x0.6 smd: 1(-2.725,1.905) 2(-2.725,0.635) 3(-2.725,-0.635) 4(-2.725,-1.905) 5(2.725,-1.905) 6(2.725,-0.635) 7(2.725,0.635) 8(2.725,1.905)
  silkscreen extent -3.3,-2.5 0.9,2.5, body extent -3,-2.45 3,2.45, height 1.63
DBV0005A_L [mm] "SOT23, 5-Leads, Body 2.9x1.6mm, Pitch 0.95mm, Lead Span 2.8mm, IPC High Density"
  rrect18% 0.8x0.55 smd: 1(-1.275,0.95) 2(-1.275,0) 3(-1.275,-0.95) 4(1.275,-0.95) 5(1.275,0.95)
  silkscreen extent -0.35,-1.55 0.35,1.55, body extent -1.42,-1.46 1.42,1.46, height 1.09
DBV0005A_N [mm] "SOT23, 5-Leads, Body 2.9x1.6mm, Pitch 0.95mm, Lead Span 2.8mm, IPC Medium Density"
  rrect17% 1x0.6 smd: 1(-1.375,0.95) 2(-1.375,0) 3(-1.375,-0.95) 4(1.375,-0.95) 5(1.375,0.95)
  silkscreen extent -0.25,-1.55 0.25,1.55, body extent -1.42,-1.46 1.42,1.46, height 1.09
DBZ0003A_N [mm] "SOT23, 3-Leads, Body 2.9x1.3mm, Pitch 0.95mm, Lead Span 2.4mm, IPC Medium Density"
  rrect17% 1x0.6 smd: 1(-1.2,0.95) 2(-1.2,-0.95) 3(1.2,0)
  silkscreen extent 0.2,-1.5 0.7,1.5, body extent -1.26,-1.46 1.26,1.46, height 0.98
DCK0005A_L [mm] "SOT353, 5-Leads, Body 2x1.3mm, Pitch 0.65mm, Lead Span 2.1mm, IPC High Density"
  rrect25% 0.65x0.4 smd: 1(-1.025,0.65) 2(-1.025,0) 3(-1.025,-0.65) 4(1.025,-0.65) 5(1.025,0.65)
  silkscreen extent -1.27,-1.09 0.56,1.09, body extent -1.14,-1 1.14,1, height 0.95
DDB0014A-MFG [mm]
  rrect17% 1.55x0.6 smd paste+0 mask+0: 1(-2.7,4.445) 3(-2.7,1.905) 4(-2.7,0.635) 5(-2.7,-0.635) 6(-2.7,-1.905) 7(-2.7,-3.175) 8(-2.7,-4.445) 9(2.7,-4.445) 10(2.7,-3.175) 11(2.7,-1.905) 12(2.7,-0.635) 14(2.7,1.905) 15(2.7,3.175) 16(2.7,4.445)
  silkscreen extent -4.12,-5 2,5, body extent -3.01,-4.95 3.01,4.95, height 1.75
DDPAK [mil] "D2-PAK, 3-Pads, Body 9.7x10.4mm (max), TO-263AB, using Vishay Silionix recommended pad sizes"
  rrect8% 135x49.49 smd: 1(-246.06,100) 3(-246.06,-100)
  rrect1% 355x420 smd paste-181.1: 4(155.51,0)
  silkscreen extent -295,-220 344,220, body extent -295,-202 324,202, height 180
DIP-4 [mm] "DIP, 4-Leads, Body 6.86x4.83mm, Pitch 2.54mm"
  rect 1.15x1.15 hole 0.65: 1(-3.81,1.27)
  round 1.15 hole 0.65: 2(-3.81,-1.27) 3(3.81,-1.27) 4(3.81,1.27)
  silkscreen extent -4,-2.41 3.43,2.52, body extent -4.02,-2.41 4.02,2.41, height 5.59
DO-41 [mm] "diode"
  rect 1.75x1.75 hole 1.15: 1(-5.08,0)
  round 1.75 hole 1.15: 2(5.08,0)
  silkscreen extent -2.62,-1.37 2.59,1.35, body extent -5.51,-1.36 5.51,1.36, height 2.72
DQJ0008A [mm] "SMD, 8-Leads, Body 5.75x4.9mm"
  rrect39% 0.91x0.51 smd paste-0.05 mask-0.05: 1(-2.795,1.905) 2(-2.795,0.635) 3(-2.795,-0.635) 4(-2.795,-1.905) 5(2.795,-1.905) 6(2.795,-0.635) 7(2.795,0.635) 8(2.795,1.905)
  rrect8% 1.58x1.25 on Bottom Paste: 9(-0.38,-1.45) 9(-0.38,0) 9(-0.38,1.45) 9(1.4,-1.45) 9(1.4,0) 9(1.4,1.45)
  rrect3% 3.48x4.47 on Bottom Solder: 9(0.55,0)
  rrect2% 4.49x4.57 smd paste-2.5 mask-2.5: 9(1.005,0)
  silkscreen extent -3,-2.6 3,2.6, body extent -3.13,-2.45 3.13,2.45, height 1.15
FCC_disclaimer [mil]
Fiducial10-20 [mm]
  round 1 smd mask+0.5: 1(0,0)
  Top Layer keep-out circle w1.178: c0,0 r0.5
FP-35ZL330MEFC10X16_RADIAL-MFG [mm]
  rrect8% 1.25x1.25 hole 0.75 paste-1000 mask+0: 1(-2.5,0)
  round 1.25 hole 0.75 paste-1000 mask+0: 2(2.5,0)
  silkscreen extent -5.25,-5.25 5.25,5.25, body extent -5.35,-5.35 5.35,5.35, height 0.25
FP-B57371V2474J060_0603-MFG [mm]
  rrect10% 1x1 smd paste+0 mask+0: 1(-1,0) 2(1,0)
  silkscreen extent -0.13,-0.48 0.13,0.48, body extent -0.8,-0.4 0.8,0.4, height 0.9
FP-KTR18EZPF3304_1206-MFG [mm]
  rrect11% 0.9x1.5 smd paste+0 mask+0: 1(-1.55,0) 2(1.55,0)
  silkscreen extent -0.72,-0.87 0.72,0.87, body extent -1.6,-0.8 1.6,0.8, height 0.65
GBU [mm] "Comchip / Diodes Inc diode bridge"
  round 2 hole 1.5: 1(-7.62,0) 2(-2.54,0) 3(2.54,0) 4(7.62,0)
  silkscreen extent -11.15,-2.28 11.15,1.28, body extent -11.15,-2.28 11.15,1.28, height 21.55
HW_1000x1600 [mm] "TH, 2-Leads, Dia 10mm, Pin Spacing 5mm"
  rect 1.35x1.35 hole 0.85: 1(-2.5,0)
  round 1.35 hole 0.85: 2(2.5,0)
  silkscreen extent -5.25,-5.25 5.25,5.25, body extent -5.25,-5.25 5.26,5.25, height 17.51
IEC_Caution_Large [mil]
  silkscreen extent -435,-375 435,378
IEC_HighVoltage_Large [mil]
  silkscreen extent -435,-352 435,401
IEC_HotSurface_Large [mil]
  silkscreen extent -435,-375 435,378
Keystone5010 [mil] "Keystone Multipurpose loops"
  round 87 hole 63: 1(0,0)
  silkscreen extent -70,-70 70,70, body extent -63,-63 63,62, height 319
Keystone5011 [mil] "Keystone Multipurpose loops"
  round 87 hole 63: 1(0,0)
  silkscreen extent -70,-70 70,70, body extent -63,-63 63,62, height 319
Keystone5012 [mil] "Keystone Multipurpose loops"
  round 87 hole 63: 1(0,0)
  silkscreen extent -70,-70 70,70, body extent -63,-63 63,62, height 319
Keystone5013 [mil] "Keystone Multipurpose loops"
  round 87 hole 63: 1(0,0)
  silkscreen extent -70,-70 70,70, body extent -63,-63 63,62, height 319
KEYSTONE_1903C [mil] "HEX NYLON STANDOFF 6-32, F-F 0.5\""
  round 1 on Mech4: 0(0,0)
  body extent -144,-125 144,125, height 501
KEYSTONE_4824 [mil] "HEX STANDOFF 6-32 NYLON 1-1/2\""
  round 1 on Mech3: 0(0,0)
  round 152 hole 152 unplated: MH(0,0)
  silkscreen extent -151,-151 151,151, body extent -144,-125 144,125, height 1500
KXG_1800x3150 [mm] "TH, 2-Leads, Dia 18mm, Pin Spacing 7.5mm"
  rect 1.55x1.55 hole 1.05: 1(-3.75,0)
  round 1.55 hole 1.05: 2(3.75,0)
  silkscreen extent -9.25,-9.25 9.25,9.25, body extent -9.18,-9.33 9.22,9.14, height 33.01
Littelfuse_TMOV20RP750E [mm] "TH, 2-Leads, Dia 20mm"
  round 1.95 hole 1.3: 1(-4.25,-1) 2(4.25,1)
  body extent -11.5,-6.5 11.5,6.5, height 27.99
On-Shore_ED120_2DS [mm] "ONSHORE"
  rrect5% 2x2 hole 1.25: 1(-2.54,0)
  round 2 hole 1.25: 2(2.54,0)
  silkscreen extent -5.6,-4 5.12,5, body extent -5.78,-4 5.08,5, height 13
On-Shore_ED120_3DS [mm] "ONSHORE"
  rrect5% 2x2 hole 1.25: 1(-5.08,0)
  round 2 hole 1.25: 2(0,0) 3(5.08,0)
  silkscreen extent -8.14,-4 7.5,5, body extent -8.32,-4 7.62,5, height 13
Panduit_CXS70-14-C [mil] "Panduit"
  rect 770x500 hole 270 copper offset -74.8,0 paste-250: 1(0,0)
  body extent -960,-250 310,250, height 684
R46_2650x1000x1850 [mm] "TH, 2-Leads, Body 26.5x10mm, Pin Spacing 22.9mm"
  round 1.65 hole 1.1: 1(-11.45,0) 2(11.45,0)
  silkscreen extent -13.4,-5.1 13.4,5.1, body extent -13.4,-5.1 13.4,5.1, height 18.6
S237 [mm] "EPCOS"
  round 1.75 hole 1.1: 1(-3.75,0) 2(3.75,0)
  silkscreen extent -7.5,-3.5 7.5,3.5, body extent -7.47,-3.5 7.47,3.5, height 21.99
SMA [mm] "Molded Diode, 2-Leads, Body 4.3x2.6mm, IPC Medium Density, based on OnSemi component dimensions and land pattern"
  rect 2x2 smd: 1(-2,0) 2(2,0)
  silkscreen extent -3.66,-1.57 2.79,1.57, body extent -2.6,-1.3 2.6,1.3, height 2.42
SMAF [mm] "SMD, 2-Leads, Body 3.8x2.5mm"
  rect 1.24x1.89 smd: 1(-2.04,0) 2(2.04,0)
  silkscreen extent -3.4,-1.3 2.8,1.3, body extent -2.35,-1.25 2.35,1.25, height 1
SOD-123 [mm] "On Semi recommended land pattern"
  rect 0.915x1.22 smd: 1(-1.637,0) 2(1.637,0)
  silkscreen extent -2.74,-1.17 2.03,1.17, body extent -1.93,-0.9 1.93,0.9, height 1.35
SOD-123W [mm] "NXP recommended land pattern"
  rect 1.2x1.2 smd paste-0.05: 1(-1.4,0) 2(1.4,0)
  silkscreen extent -2.64,-1.14 1.68,1.14, body extent -1.85,-0.95 1.85,0.95, height 1.1
SOT-23L [mm] "SOT23, 3-Leads, Body 2.9x1.3mm, Pitch 0.95mm, Lead Span 2.5mm, IPC High Density"
  rrect50% 0.8x0.6 smd: 1(-1.1,0.95) 2(-1.1,-0.95) 3(1.1,0)
  silkscreen extent -1.5,-1.5 0.7,1.5, body extent -1.16,-1.45 1.21,1.45, height 1
TI_Stacked_Overlay_Small [mil]
  silkscreen extent -418,-98 418,98
TO-220AB_100mil [mm] "High Voltage staggered pins"
  rrect50% 1.8x1.8 hole 1.3: 1(-2.54,0)
  round 1.8 hole 1.3: 2(0,-2.54) 3(2.54,0)
  silkscreen extent -5.77,-1.62 5.44,3.07, body extent -5.77,-2.84 5.53,3.07, height 21.61
WEEE_Minimum [mil] "WEEElie bin"
  silkscreen extent -95,-172 99,104
Wurth_750344018 [mm] "TH, 14-Leads, Body 43x36.5mm, Pitch 5.8mm"
  rrect50% 2.4x2.4 hole 1.6: 1(-13.95,17.4)
  round 2.4 hole 1.6: 2(-13.95,11.6) 3(-13.95,5.8) 4(-13.95,0) 5(-13.95,-5.8) 6(-13.95,-11.6) 7(-13.95,-17.4) 8(13.95,-17.4) 9(13.95,-11.6) 10(13.95,-5.8) 11(13.95,0) 12(13.95,5.8) 13(13.95,11.6) 14(13.95,17.4)
  body extent -18.25,-21.5 18.25,21.5, height 26.5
